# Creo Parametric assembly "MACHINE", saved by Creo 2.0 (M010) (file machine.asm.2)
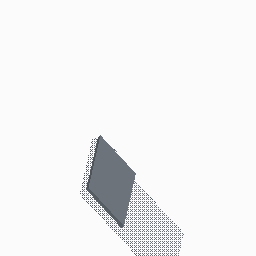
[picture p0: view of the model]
Units: Inch lbm Second (Pro/E Default); INCH, POUND, SECS

Created from: INLBS_ASM_DESIGN.ASM

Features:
  1. datum plane "ASM_RIGHT"
  2. datum plane "ASM_TOP"
  3. datum plane "ASM_FRONT"
  4. coordinate system
  5. component "YMOTOR"
  6. coordinate system
  7. component "BASE_BOARD"
  8. component "TOPBOARD"

Other named items: ACS0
